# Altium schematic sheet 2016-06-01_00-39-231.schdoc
size 349 x 190 mm; SheetNumber: 1; SheetTotal: 1
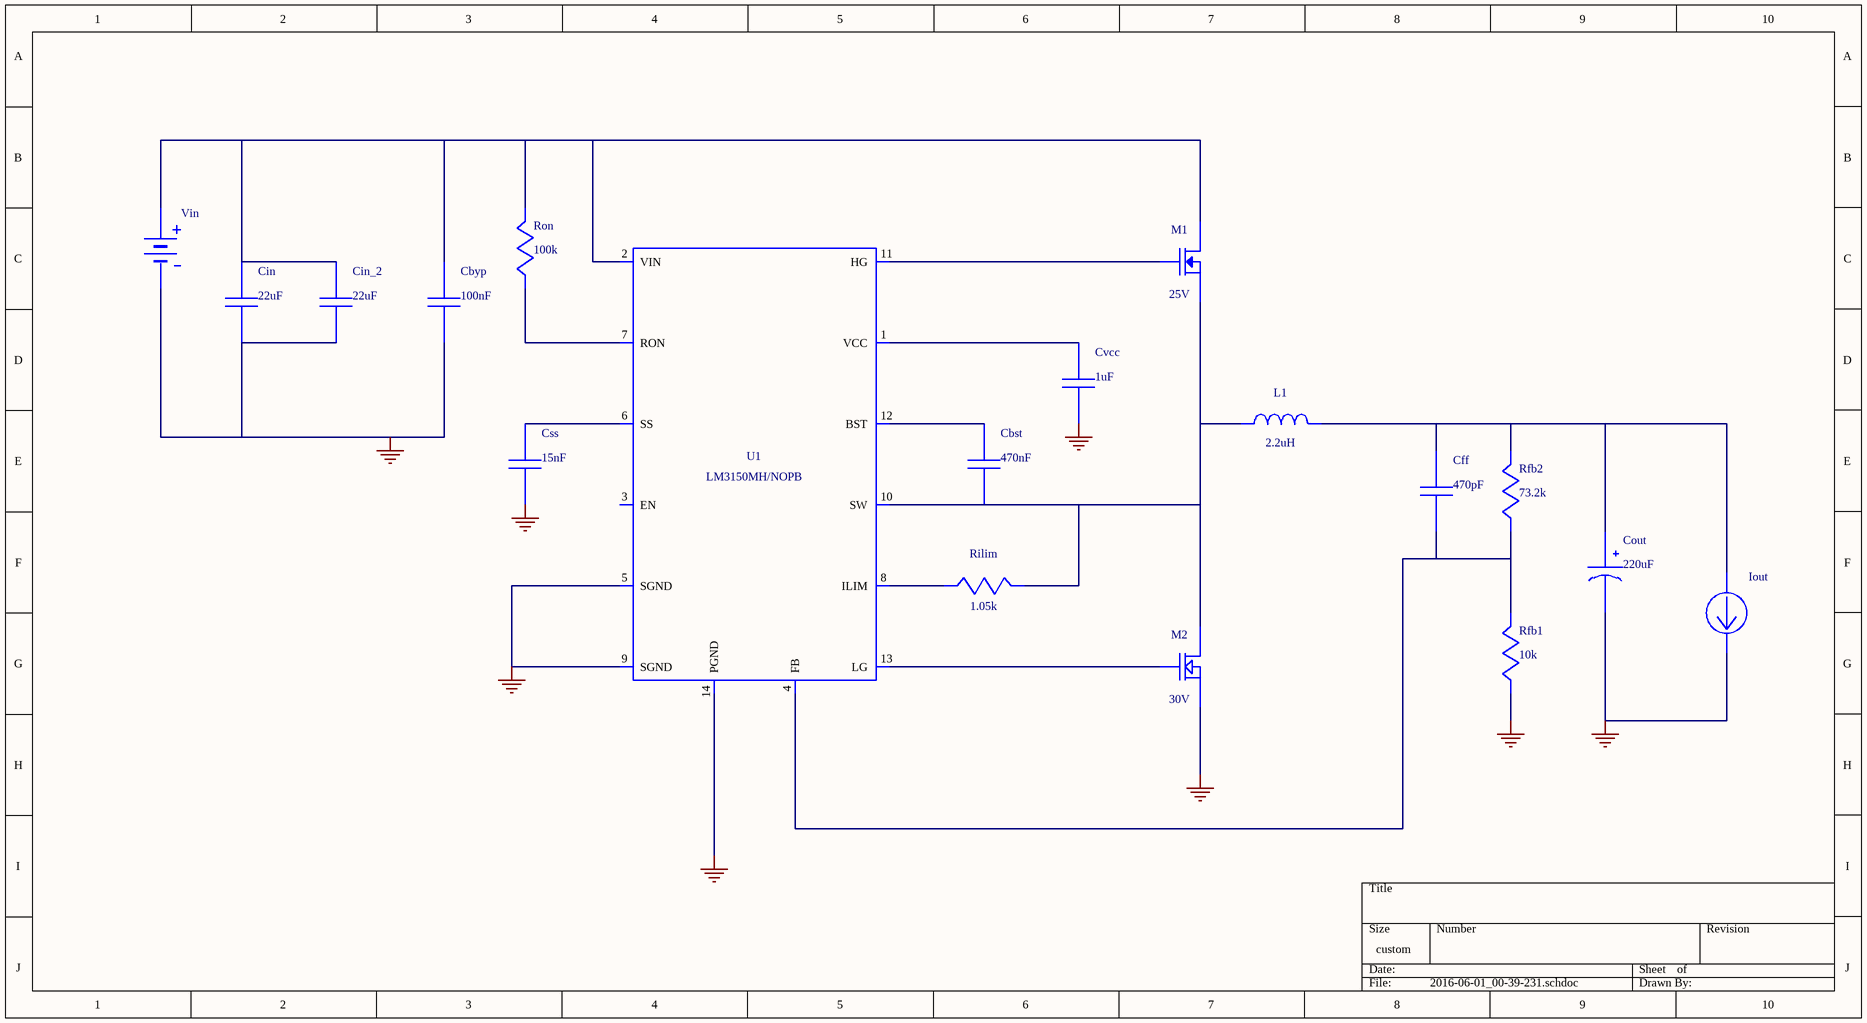
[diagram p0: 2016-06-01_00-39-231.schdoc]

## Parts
Cbst  value 470nF  (hidden comment: EMK212B7474KD-T)
Cbyp  value 100nF  (hidden comment: 08053C104KAT2A)
Cff  value 470pF  (hidden comment: C0805C471K5RACTU)
Cin  value 22uF  (hidden comment: GRM32ER61E226KE15L)
Cin_2  value 22uF  (hidden comment: GRM32ER61E226KE15L)
Cout  value 220uF  (hidden comment: 6SVPE220MW)
Css  value 15nF  (hidden comment: CC0805KRX7R9BB153)
Cvcc  value 1uF  (hidden comment: EMK212B7105KG-T)
Iout  WB_CURRENT_LOAD  (value not drawn)
L1  value 2.2uH  (hidden comment: SRP1270-2R2M)
M1  value 25V  (hidden comment: CSD16342Q5A)
M2  value 30V  (hidden comment: CSD17577Q5A)
Rfb1  value 10k  (hidden comment: ERJ-6ENF1002V)
Rfb2  value 73.2k  (hidden comment: ERJ-6ENF7322V)
Rilim  value 1.05k  (hidden comment: ERJ-6ENF1051V)
Ron  value 100k  (hidden comment: ERJ-6ENF1003V)
U1  LM3150MH/NOPB
Vin  WB_BATTERY  (value not drawn)

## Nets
0: Cbyp.2 Cin.2 Cin_2.2 Cout.2(-) Css.2 Cvcc.2 Iout.2(-) M2.1(Source) M2.2(Source) M2.3(Source) Rfb1.2 U1.5(SGND) U1.9(SGND) U1.14(PGND) U1.15(DAP) Vin.2(-)
NetCbst_1: Cbst.1 U1.12(BST)
NetCbst_2: Cbst.2 L1.1 M1.1(Source) M1.2(Source) M1.3(Source) M2.5(Drain) M2.6(Drain) M2.7(Drain) M2.8(Drain) M2.9(Drain) Rilim.1 U1.10(SW)
NetCbyp_1: Cbyp.1 Cin.1 Cin_2.1 M1.5(Drain) M1.6(Drain) M1.7(Drain) M1.8(Drain) M1.9(Drain) Ron.1 U1.2(VIN) Vin.1(+)
NetCff_1: Cff.1 Cout.1(+) Iout.1(+) L1.2 Rfb2.1
NetCff_2: Cff.2 Rfb1.1 Rfb2.2 U1.4(FB)
NetCss_1: Css.1 U1.6(SS)
NetCvcc_1: Cvcc.1 U1.1(VCC)
NetM1_4: M1.4(Gate) U1.11(HG)
NetM2_4: M2.4(Gate) U1.13(LG)
NetRilim_2: Rilim.2 U1.8(ILIM)
NetRon_2: Ron.2 U1.7(RON)

Not connected (* = marked no-connect by the designer): U1 3(EN)

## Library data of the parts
Cbst = EMK212B7474KD-T: Manufacturer Name: Taiyo Yuden
Cbyp = 08053C104KAT2A: Manufacturer Name: AVX
Cff = C0805C471K5RACTU: Manufacturer Name: Kemet
Cin Cin_2 = GRM32ER61E226KE15L: GRM32ER61E226KE1; Manufacturer Name: MuRata
Cout = 6SVPE220MW: Manufacturer Name: Panasonic
Css = CC0805KRX7R9BB153: CC0805KRX7R9BB15; Manufacturer Name: Yageo America
Cvcc = EMK212B7105KG-T: Manufacturer Name: Taiyo Yuden
Iout = WB_CURRENT_LOAD: Value: UNLISTED
L1 = SRP1270-2R2M: Manufacturer Name: Bourns
M1 = CSD16342Q5A: Manufacturer Name: Texas Instruments
M2 = CSD17577Q5A: Manufacturer Name: Texas Instruments
Rfb1 = ERJ-6ENF1002V: Manufacturer Name: Panasonic
Rfb2 = ERJ-6ENF7322V: Manufacturer Name: Panasonic
Rilim = ERJ-6ENF1051V: Manufacturer Name: Panasonic
Ron = ERJ-6ENF1003V: Manufacturer Name: Panasonic
U1 = LM3150MH/NOPB: Manufacturer Name: Texas Instruments; Value: UNLISTED
Vin = WB_BATTERY: Value: UNLISTED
